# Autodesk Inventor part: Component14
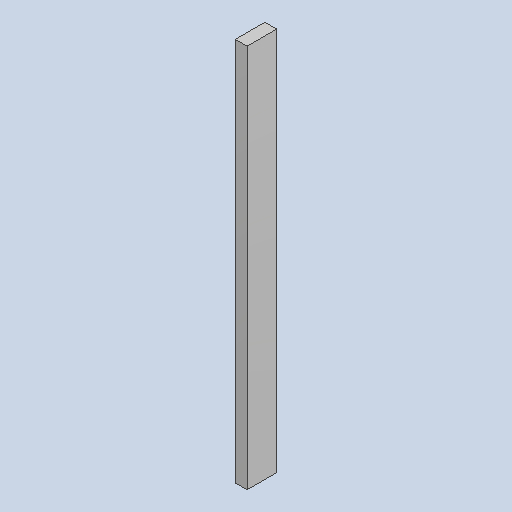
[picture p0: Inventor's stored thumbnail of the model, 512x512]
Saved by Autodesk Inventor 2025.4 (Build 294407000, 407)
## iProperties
Created: 2026-06
Part Number: Component14
Material: Generic
Document SubType Name: Modeling
Designer: AdminForWorker
Density: 1 g/cm^3
Appearance: Default
Title: Component14
Author: AdminForWorker
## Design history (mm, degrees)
feature "Body1"
body "Solid1"
